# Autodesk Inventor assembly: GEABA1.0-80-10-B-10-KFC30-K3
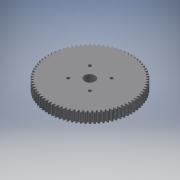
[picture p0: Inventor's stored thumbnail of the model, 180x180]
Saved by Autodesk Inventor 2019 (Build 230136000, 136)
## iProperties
Category: PARTsolutions
Company: MISUMI
Created: 2022-11
Part Number: GEABA1.0-80-10-B-10-KFC30-K3
Catalog Web Link: www.cadenas.de
Description: GEABM, GEABMS, GEABMT, GEABP, GEABPS, GEABPT, GEABA, GEABAS, GEABAT-Plastic Spur Gears - Pressure Angle 20 Degrees, Module 0.5/0.8/1.0/1.5/2.0/2.5/3.0
Vendor: MISUMI
Document SubType Name: Assembly
Designer: psAdmin
Manufacturer: MISUMI
Mass: 60.3551 g
Surface Area: 175.026 cm^2
Volume: 60.3551 cm^3
Density: 1 g/cm^3
Title: GEABA1.0-80-10-B-10-KFC30-K3
Author: Cadenas PARTsolutions
Comments: Plastic Spur Gears - Pressure Angle 20 Degrees, Module 0.5/0.8/1.0/1.5/2.0/2.5/3.0
PSOL_IDENT_0: {$CADENAS_DATA/23d-libs/misumi/metric/54_spur_gears/geabms20_asmtab.prj},415 {VTYP=3D},{STYP=ASSTAB}
PSOL_IDENT_1: ,{NB=GEABA1.0-80-10-B-10-KFC30-K3},{LINA=GEABA1.0-80-10-B-10-KFC30-K3},{NN=GEABM, GEABMS, GEABMT, GE
PSOL_IDENT_2: ABP, GEABPS, GEABPT, GEABA, GEABAS, GEABAT},{DATE=16.08.2021 10:08:31},{GEOMDATE=16.08.2021 10:08:28
PSOL_IDENT_3: },{VERSION=},{LINEID=30},{WBVAR=MATSG,MATCR,NT,B,TS,PS,ALT1,ALT2,TPC,ALT11,ALT10,BS,ALT3,Z,J,ALT4,Q,
PSOL_IDENT_4: R,S,T,ALT5,LFC,LTC,MALT5,ALT6,KFC,KTC,K},{WBNUMERIC=NT,B,BS,Z,J,Q,R,S,T,LFC,LTC,KFC,KTC,K}  {NB=GEAB
PSOL_IDENT_5: A1.0-80-10-B-10-KFC30-K3},{LINA=GEABA1.0-80-10-B-10-KFC30-K3},{KT=DUMMY},{PN=GEABA1.0-80-10-B-10-KFC
PSOL_IDENT_6: 30-K3},{TYPE=GEABA},{MATSG=PB},{MATSGALG='MCN','MC Nylon','PW','Polyacetal White','PB','Polyacetal B
PSOL_IDENT_7: lue'},{MATCR=},{MATCRALG='','-','S45C','1045 Carbon Steel','SUS304','304 Stainless Steel'},{MOD=1.0}
PSOL_IDENT_8: ,{MOD1=1.0},{NT=80},{NTALG=15,16,18,20,22,24,25,26,28,30,32,35,36,40,45,48,50,55,60,70,75,80,90,100,
PSOL_IDENT_9: 120},{B=10},{BALG=10,15},{TS=B},{TSALG='A','A','B','B'},{TSPN=-B},{PS=10},{PSALG='10','10','11','11'
PSOL_IDENT_10: ,'12','12','13','13','14','14','15','15','16','16','17','17','18','18','19','19','20','20','21','21'
PSOL_IDENT_11: ,'22','22','23','23','24','24','25','25','26','26','27','27','28','28'},{PSCRL='10','10','11','11','
PSOL_IDENT_12: 12','12','13','13','14','14','15','15','16','16','17','17','18','18','19','19','20','20','21','21','
PSOL_IDENT_13: 22','22','23','23','24','24','25','25','26','26','27','27','28','28'},{PSCRW='10','10','12','12','15'
PSOL_IDENT_14: ,'15','20','20'},{DD=80.0},{DD05=40},{DD08=64},{DD10=80},{DD15=120},{DD20=0},{DD25=0},{DD30=0},{D=82
PSOL_IDENT_15: .0},{D05=41},{D08=65.6},{D10=82},{D15=123},{D20=0},{D25=0},{D30=0},{G=77.50},{G05=38.75},{G08=62},{G
PSOL_IDENT_16: 10=77.5},{G15=116.25},{G20=0},{G25=0},{G30=0},{H=40.0},{L=20},{LL1=10},{LL2=4.0},{M=M4},{M3D=4},{P=1
PSOL_IDENT_17: 0.00},{DD1=0},{CIFR=15},{CIFM=4},{CIFK=0},{CIFTAP=1},{SCREW=4.000},{SCREWL=3.000},{ALT1=},{ALT1ALG=''
PSOL_IDENT_18: ,'w/o Set Screw','KC90','with KC90 (Set Screw)','KC120','with KC120 (Set Screw)'},{ALT1PN=},{ALT2=},
PSOL_IDENT_19: {ALT2ALG='','w/o TPC (Tapped Hole Dimension)','TPC','with TPC (Tapped Hole Dimension)'},{TPC=N/A},{T
PSOL_IDENT_20: PCALG='N/A'},{ALT2PN=},{KC=0},{ALT11=},{ALT11ALG='', 'w/o GBA (Gear bottom adjustment of phase focus
PSOL_IDENT_21: )', 'GBA', 'with GBA (Gear bottom adjustment of phase focus)' },{ALT11PN=},{DEG=0},{ALT10=},{ALT10AL
PSOL_IDENT_22: G= '','w/o BS (Boss Cut)','BS','with BS (Boss Cut)' },{ALT10PN=},{BS=0.0},{BSALG=0},{BSMIN=7.000},{B
PSOL_IDENT_23: SMINALG=7},{BSMAX=10},{LL13D=10},{LL23D=16},{ALT3=},{ALT3ALG= '','w/o Stepped Hole','DHL','with DHL
PSOL_IDENT_24: (Stepped Hole)','DHR','with DHR (Stepped Hole)' },{ALT3PN=},{ZJPN=},{ALT31=1},{ALT32=1},{Z=0},{ZALG=
PSOL_IDENT_25: 0},{ZMINL=12},{ZMAXL=73},{ZMINR=12},{ZMAXR=36},{ZPN=},{J=0.0},{JALG=0},{JMIN=2},{JMAX=0},{JPN=},{ALT
PSOL_IDENT_26: 4=},{ALT4ALG= '','w/o WDH (Both Ends Stepped Hole)','WDH','with WDH (Both Ends Stepped Hole)' },{ALT
PSOL_IDENT_27: 4PN=},{QRSTPN=},{LB=20.000},{Q=0},{QALG=0},{QMIN=12},{QMAX=36},{QPN=},{R=0},{RALG=0},{RMIN=12},{RMAX=
PSOL_IDENT_28: 36},{RPN=},{S=0},{SALG=0},{SMIN=3},{SMAX=14},{SPN=},{T=0},{TALG=0},{TMIN=3},{TMAX=0},{TPN=},{ALT5=},
PSOL_IDENT_29: {ALT5ALG= '','Not applicable' },{LFC=0},{LFCALG=0},{LTC=0},{LTCALG=0},{LPCDMIN=18},{LPCDMAX=70},{LCM
PSOL_IDENT_30: AX=73},{MALT5=N/A},{MALT5ALG= 'N/A' },{LCMAX2=70},{C=0.0},{ALT5PN=},{ALT6=KFC},{ALT6ALG= '','w/o Sid
PSOL_IDENT_31: e Through Hole','KFC','with KFC (Side Through Hole)','KTC','with KTC (Side Through Hole)' },{ALT6PN=
PSOL_IDENT_32: -KFC},{KFTCPN=30-K3},{KFC=30},{KFCALG=[17:33/1],[47:70/1]},{KFCPN=30},{KTC=0},{KTCALG=[0]},{KTCPN=},
PSOL_IDENT_33: {KPCDMIN1=17},{KPCDMAX1=33},{KPCDMIN2=47},{KPCDMAX2=70},{K=3.0},{KALG=[3:6/0.5]},{KPCD=30},{KPN=-K3}
PSOL_IDENT_34: ,{AG=0},{LBS=20},{PCD=30},{SHN=4},{SHDEG1=45},{SHDEG2=90},{PZQRDD2=10},{PPATH=geabms20/geabms20_asmt
PSOL_IDENT_35: pl.prj}
NB: GEABA1.0-80-10-B-10-KFC30-K3
NN: GEABM, GEABMS, GEABMT, GEABP, GEABPS, GEABPT, GEABA, GEABAS, GEABAT
NT: 80
NBSYN: $PN.
LINA: GEABA1.0-80-10-B-10-KFC30-K3
CATALOG: Misumi
PN: GEABA1.0-80-10-B-10-KFC30-K3
MATSG: Polyacetal Blue
MATCR: -
MOD: 1.0
B: 10
TS: B
PS: 10
DD: 80
D: 82
G: 77.5
H: 40
L: 20
LL1: 10
LL2: 4
M: M4
DD1: 0
ALT1: w/o Set Screw
ALT2: w/o TPC (Tapped Hole Dimension)
TPC: N/A
ALT11: w/o GBA (Gear bottom adjustment of phase focus)
ALT10: w/o BS (Boss Cut)
BS: 0
ALT3: w/o Stepped Hole
Z: 0
J: 0
ALT4: w/o WDH (Both Ends Stepped Hole)
Q: 0
R: 0
S: 0
T: 0
ALT5: Not applicable
LFC: 0
LTC: 0
MALT5: N/A
C: 0
ALT6: with KFC (Side Through Hole)
KFC: 30
KTC: 0
K: 3
SUPPLIER: MISUMI
ARTICLENO: GEABA1.0-80-10-B-10-KFC30-K3
BOMINFO: GEABA1.0-80-10-B-10-KFC30-K3
CREATOR: CADENAS GmbH
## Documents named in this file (3)
- e:\temp\worker_COMMON_12\temp\tmp_7100_78_GfJPW\format_0\GEABA1_0-80-10-B-10-KFC30-K3.iam
- e:\temp\worker_COMMON_12\temp\tmp_7100_78_GfJPW\format_0\GEABA1_0-80-10-B-10-KFC30-K3_b.ipt
- e:\temp\worker_COMMON_12\temp\tmp_7100_78_GfJPW\format_0\SET-SCREW4-3.ipt
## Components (2 placed, 2 different names)
1. GEABA1_0-80-10-B-10-KFC30-K3_b:1 — gear_to_screw_XY@1 <-> CP_XY@2, gear_to_screw_Z@1 <-> CP_Z@2, gear_to_screw_YZ@1 <-> CP_YZ@2
2. SET-SCREW4-3:1 — gear_to_screw_XY@1 <-> CP_XY@2, gear_to_screw_Z@1 <-> CP_Z@2, gear_to_screw_YZ@1 <-> CP_YZ@2
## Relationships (3: Mate 2, Angle 1)
- gear_to_screw_XY@1 <-> CP_XY@2 [Mate]: GEABA1_0-80-10-B-10-KFC30-K3_b:1 ↔ SET-SCREW4-3:1
- gear_to_screw_Z@1 <-> CP_Z@2 [Mate]: GEABA1_0-80-10-B-10-KFC30-K3_b:1 ↔ SET-SCREW4-3:1
- gear_to_screw_YZ@1 <-> CP_YZ@2 [Angle]: GEABA1_0-80-10-B-10-KFC30-K3_b:1 ↔ SET-SCREW4-3:1
